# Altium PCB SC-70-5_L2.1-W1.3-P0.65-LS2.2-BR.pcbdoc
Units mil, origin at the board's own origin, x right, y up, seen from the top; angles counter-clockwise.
Board outline 641.03 x 600.28 mil, 2 copper layers (Top Layer, Bottom Layer), stack 0 mil thick; 1 components, 0 nets, 5 pads, 0 vias.
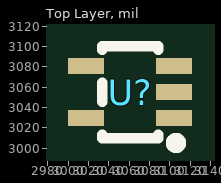
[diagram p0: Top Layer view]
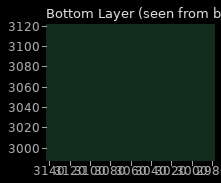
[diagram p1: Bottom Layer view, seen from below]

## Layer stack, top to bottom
Top Layer: signal copper (thickness not stored)
Bottom Layer: signal copper (thickness not stored)

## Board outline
3391.03,2750 2750,2750 2750,3350.28 3391.03,3350.28

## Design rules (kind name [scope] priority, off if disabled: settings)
PasteMaskExpansion "Paste Mask Expansion" [All] p1: expansion=0
SolderMaskExpansion "Solder Mask Expansion" [IsVia] p1: expansion=-1000 istentingtop=TRUE
SolderMaskExpansion "Solder Mask Expansion" [All] p2: expansion=2 istentingtop=FALSE

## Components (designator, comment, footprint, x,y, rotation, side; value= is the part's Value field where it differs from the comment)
U? "" SC-70-5_L2.1-W1.3-P0.65-LS2.2-BR 3061.03,3055 r0 top

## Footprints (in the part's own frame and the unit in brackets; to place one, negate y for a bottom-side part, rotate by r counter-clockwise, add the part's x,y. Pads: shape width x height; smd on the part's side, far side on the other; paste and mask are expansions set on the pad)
SC-70-5_L2.1-W1.3-P0.65-LS2.2-BR [mm]
  rect 0.9x0.4 smd: 1(1.1,-0.65) 2(1.1,0) 3(1.1,0.65) 4(-1.1,0.65) 5(-1.1,-0.65)
  silkscreen extent -0.7,-1.4 1.27,1.15

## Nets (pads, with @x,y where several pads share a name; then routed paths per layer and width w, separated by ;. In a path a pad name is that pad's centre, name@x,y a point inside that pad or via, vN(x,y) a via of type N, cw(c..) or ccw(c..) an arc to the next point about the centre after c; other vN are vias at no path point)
pads on no net: U?.1 U?.2 U?.3 U?.4 U?.5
